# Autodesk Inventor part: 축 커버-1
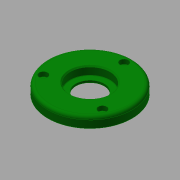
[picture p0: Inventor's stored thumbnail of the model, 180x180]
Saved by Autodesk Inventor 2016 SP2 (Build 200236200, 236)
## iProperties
Created: 2015-10
Part Number: 축 커버-1
Document SubType Name: Modeling
Designer: mdu
Density: 7.86 g/cm^3
Material: 강철, 연강
Appearance: 진녹색
Mass: 324.903 g
Surface Area: 132.124 cm^2
Volume: 41.3362 cm^3
Author: mdu
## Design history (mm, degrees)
sketch "스케치1"
  geometry: C1 r 40 at (0, 0) reference; C2 r 26 at (0, 0) reference; 1 further point
  node "참조1"
  node "참조2"
extrude "돌출1" new body sketch "스케치1" distance "d0" = 10; taper "d1" = 0 deg
extrude "돌출2" join sketch "스케치1" distance "d2" = 3; taper "d3" = 0 deg
hole "구멍1" diameter "d6" = 27; stored, may be unused: countersink angle "d10" = 90 deg, drill point angle "d12" = 118 deg; dims "d4" = 10, "d5" = 10, "d7" = 6, "d8" = 38, "d9" = 8, "d11" = 8
sketch "스케치2"
  geometry: C1 r 20 at (0, 0); 1 further point
  constraints: 1 centre point, 1 coincident
  dimensions: "d13" = 40 diameter of C1
extrude "돌출3" cut sketch "스케치2" distance "d14" = 3; taper "d15" = 0 deg
sketch "스케치3"
  geometry: C1 r 1.621 at (0, 32.5) reference; 1 further point
hole "구멍2" sketch "스케치3" at (0, 32.5) diameter "d16" = 4.5; stored, may be unused: countersink angle "d20" = 90 deg, drill point angle "d22" = 118 deg; dims "d17" = 6, "d18" = 8, "d19" = 4.4, "d21" = 8
fillet "모깎기1" dims "d26" = 3, "d27" = 0.3
chamfer "모따기1" distance "d28" = 1; stored, may be unused: second distance "d29" = 2, angle "d30" = 45 deg
node "솔리드1"
pattern_circular "원형 패턴1" dims angle "d24" = 360 deg
node "참조3"
